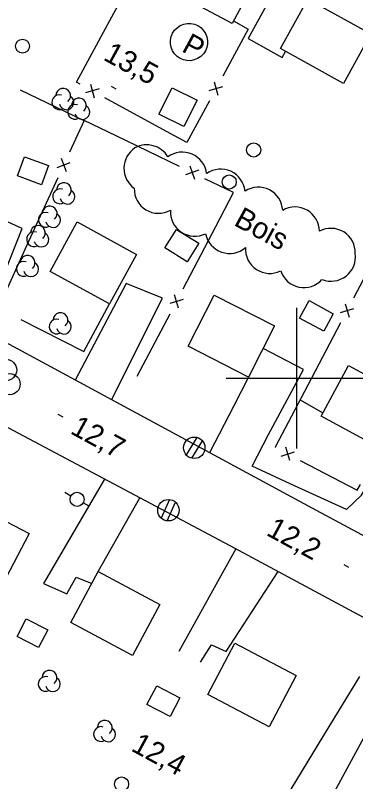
# Model space of a CAD drawing. Extents: x 219136 to 222520, y 5421589 to 5424530.
# Drawn here: x 220760 to 220808.4, y 5423742.7 to 5423851.5 of the extents above; entities that cross this region are included whole.
import ezdxf

# ---------------------------------------------------------------- set-up
doc = ezdxf.new("R2010")
doc.units = 0
for name, color, linetype in [('Level 19', 7, 'Continuous'), ('Level 21', 7, 'Continuous'), ('Level 3', 7, 'Continuous'), ('Level 31', 7, 'Continuous'), ('Level 36', 7, 'Continuous'), ('Level 37', 7, 'Continuous'), ('Level 38', 7, 'Continuous'), ('Level 44', 7, 'Continuous'), ('Level 61', 7, 'Continuous')]:
    doc.layers.add(name, color=color, linetype=linetype)

msp = doc.modelspace()

# ---------------------------------------------------------------- linework, layer by layer
at = {"layer": 'Level 19'}
for points in [[(220802.57, 5423865.48), (220793.1, 5423848.23), (220797.96, 5423845.52), (220798.42, 5423846.39)], [(220755.21, 5423806.76), (220761, 5423821.25), (220755.05, 5423823.88)], [(220773.67, 5423796.92), (220780.95, 5423811.36), (220775.79, 5423813.44), (220768.51, 5423799.7)], [(220793.68, 5423787.51), (220795.99, 5423792.01), (220800.96, 5423801.23), (220795.24, 5423804.2)], [(220793.17, 5423800.13), (220791.08, 5423796.04), (220787.59, 5423789.41)], [(220807.06, 5423781.33), (220809.21, 5423783.37), (220813.55, 5423790.78), (220817.55, 5423797.92), (220823.91, 5423794.35)], [(220772.67, 5423785.65), (220764.02, 5423770.85), (220767.36, 5423769.35), (220768.68, 5423771.74), (220770.89, 5423770.83)], [(220771.79, 5423772.53), (220777.71, 5423782.98)], [(220791.36, 5423775.74), (220783.25, 5423761.17)], [(220786.35, 5423759.65), (220787.88, 5423762.11), (220789.96, 5423761.17), (220797.37, 5423772.51)], [(220811.71, 5423752.96), (220805.01, 5423740.58), (220808.49, 5423738.12), (220812.45, 5423743.9), (220814.7, 5423746.55), (220816.11, 5423745.96)]]:
    msp.add_lwpolyline(points, dxfattribs=at)
at = {"layer": 'Level 21'}
for points in [[(220948.95, 5423703), (220904.47, 5423726.78), (220853.86, 5423753.84), (220802.2, 5423781.53), (220756.87, 5423805.98), (220752.54, 5423808.02), (220749.08, 5423809.42), (220742.93, 5423811.71), (220736.7, 5423813.64), (220729.21, 5423815.61), (220722.71, 5423817.16), (220715.9, 5423818.25), (220709.13, 5423819.02), (220700.46, 5423819.59), (220693.39, 5423819.74), (220687.57, 5423819.54), (220678.98, 5423818.61), (220672.46, 5423817.66), (220660.87, 5423814.84)], [(220837.82, 5423743.23), (220837.67, 5423747.47), (220836.68, 5423750.08), (220835.42, 5423751.94), (220834.1, 5423752.79), (220790.53, 5423776.18), (220757.42, 5423793.74), (220751.89, 5423796.6), (220745.6, 5423799.45), (220739.31, 5423801.83), (220731.18, 5423804.33), (220723.66, 5423806.27), (220711.25, 5423808.22), (220700.8, 5423809.13), (220692.45, 5423809.16), (220680.51, 5423808.54), (220669.68, 5423806.84), (220660.39, 5423804.75)], [(220807.06, 5423781.33), (220799.71, 5423784.69), (220793.68, 5423787.51)]]:
    msp.add_lwpolyline(points, dxfattribs=at)
at = {"layer": 'Level 3'}
for p, q in [((220773.62, 5423841.46), (220774.31, 5423841.08)), ((220766.06, 5423794.86), (220766.76, 5423794.48)), ((220806.69, 5423773.54), (220807.39, 5423773.16))]:
    msp.add_line(p, q, dxfattribs=at)
at = {"layer": 'Level 31'}
for points in [[(220790.84, 5423850.38), (220781.93, 5423855.16), (220785.84, 5423862.45), (220788.61, 5423860.97), (220789.07, 5423861.82), (220791.43, 5423860.55), (220790.94, 5423859.65), (220794.72, 5423857.62)], [(220806.65, 5423841.82), (220797.68, 5423846.8), (220801.59, 5423853.85), (220810.56, 5423848.88)], [(220783.96, 5423835.71), (220780.43, 5423837.48), (220782.31, 5423841.22), (220785.84, 5423839.45)], [(220761.31, 5423831.44), (220764.73, 5423830.18), (220763.73, 5423827.47), (220760.31, 5423828.73)], [(220773.38, 5423810.53), (220764.95, 5423815.15), (220768.8, 5423822.18), (220777.23, 5423817.55)], [(220782.9, 5423821.12), (220786.08, 5423819.16), (220784.46, 5423816.53), (220781.28, 5423818.49)], [(220793.17, 5423800.13), (220784.56, 5423804.52), (220788.27, 5423811.79), (220796.87, 5423807.4)], [(220801.77, 5423811), (220805.19, 5423809.14), (220803.85, 5423806.65), (220800.42, 5423808.51)], [(220811.96, 5423789.98), (220803.48, 5423794.58), (220807.38, 5423801.77), (220815.86, 5423797.18)], [(220753.23, 5423782.48), (220761.98, 5423777.92), (220758.1, 5423770.48), (220749.35, 5423775.04)], [(220771.79, 5423772.53), (220780.54, 5423767.87), (220776.68, 5423760.62), (220767.93, 5423765.27)], [(220763.33, 5423761.72), (220760.27, 5423763.32), (220761.58, 5423765.82), (220764.64, 5423764.23)], [(220791.22, 5423762.37), (220799.92, 5423757.78), (220796.07, 5423750.48), (220787.37, 5423755.07)], [(220782, 5423751.93), (220778.73, 5423753.64), (220780.13, 5423756.31), (220783.4, 5423754.6)]]:
    msp.add_lwpolyline(points, close=True, dxfattribs=at)
at = {"layer": 'Level 36'}
for p, q in [((220785.81, 5423791.57), (220784.3, 5423789.1)), ((220785.09, 5423788.63), (220786.6, 5423791.1)), ((220767.05, 5423783.78), (220767.92, 5423783.28)), ((220770.53, 5423781.8), (220769.65, 5423782.28)), ((220781.92, 5423782.74), (220780.75, 5423780.09)), ((220781.6, 5423779.74), (220782.77, 5423782.39))]:
    msp.add_line(p, q, dxfattribs=at)
for centre, radius in [((220761.04, 5423847.14), 1), ((220793.89, 5423832.4), 1), ((220790.42, 5423827.85), 1), ((220758.72, 5423801.15), 1.5), ((220759.21, 5423799.14), 1.5), ((220785.44, 5423790.1), 1.52), ((220768.79, 5423782.78), 1), ((220781.77, 5423781.24), 1.52), ((220775.12, 5423742.35), 1)]:
    msp.add_circle(centre, radius, dxfattribs=at)
at = {"layer": 'Level 37'}
for p, q in [((220788.26, 5423842.08), (220788.82, 5423840.16)), ((220771.92, 5423841.06), (220770, 5423840.49)), ((220770.68, 5423841.73), (220771.24, 5423839.81)), ((220787.58, 5423840.84), (220789.5, 5423841.41)), ((220766.55, 5423831.22), (220767.24, 5423829.34)), ((220765.95, 5423829.93), (220767.83, 5423830.63)), ((220784.82, 5423830.13), (220785.48, 5423828.24)), ((220786.09, 5423829.52), (220784.2, 5423828.86)), ((220783.23, 5423809.93), (220782.63, 5423811.84)), ((220783.88, 5423811.18), (220781.97, 5423810.59)), ((220806.88, 5423810.55), (220807.47, 5423808.64)), ((220806.21, 5423809.3), (220808.13, 5423809.89)), ((220799.05, 5423788.28), (220798.45, 5423790.19)), ((220797.79, 5423788.93), (220799.7, 5423789.53))]:
    msp.add_line(p, q, dxfattribs=at)
for points in [[(220773.18, 5423850.28), (220777.38, 5423858.03), (220778.44, 5423857.49)], [(220791.02, 5423850.72), (220793.12, 5423849.56), (220789.49, 5423842.88)], [(220769.21, 5423841.73), (220768.69, 5423842.01), (220773.18, 5423850.28)], [(220769.78, 5423836.55), (220760.77, 5423840.89)], [(220781.5, 5423835.03), (220772.72, 5423839.82)], [(220787.59, 5423839.36), (220784.38, 5423833.46), (220781.5, 5423835.03)], [(220774.34, 5423834.41), (220769.8, 5423836.6), (220767.73, 5423832.1)], [(220783.35, 5423830.06), (220774.34, 5423834.41)], [(220766.06, 5423828.46), (220761.88, 5423819.38)], [(220788.5, 5423821.51), (220791.04, 5423826.34), (220786.95, 5423828.32)], [(220783.86, 5423812.66), (220788.5, 5423821.51)], [(220761.88, 5423819.38), (220757.7, 5423810.29)], [(220814.52, 5423814.66), (220810.84, 5423816.55), (220808.1, 5423811.36)], [(220769.74, 5423803.8), (220769.77, 5423803.79), (220773.38, 5423810.53)], [(220760.82, 5423808.33), (220769.74, 5423803.8)], [(220777.35, 5423800.26), (220782, 5423809.11)], [(220806.24, 5423807.83), (220801.57, 5423798.98)], [(220801.57, 5423798.98), (220796.93, 5423790.18), (220796.97, 5423790.16)], [(220800.48, 5423796.9), (220803.74, 5423795.05)], [(220800.52, 5423788.31), (220808.59, 5423784.1), (220809.05, 5423784.88)], [(220803.76, 5423749.09), (220808.97, 5423757.63)], [(220798.56, 5423740.55), (220803.76, 5423749.09)]]:
    msp.add_lwpolyline(points, dxfattribs=at)
at = {"layer": 'Level 38'}
msp.add_ellipse((220784.69, 5423847.72), major_axis=(-1.24, 2.34), ratio=0.999955, dxfattribs=at)
at = {"layer": 'Level 44'}
for centre, radius, start, end in [((220766.81, 5423840.09), 1.05, 310.1588, 177.6158), ((220766.26, 5423839.2), 1.05, 72.005, 297.6935), ((220767.3, 5423839.16), 1.05, 194.8265, 57.5108), ((220768.51, 5423837.83), 1.05, 72.005, 297.6935), ((220769.06, 5423838.72), 1.05, 310.1588, 177.6158), ((220769.55, 5423837.79), 1.05, 194.8265, 57.5108), ((220778.91, 5423829.79), 3.46, 123.313, 234.8249), ((220778.71, 5423829.67), 3.46, 30.1731, 119.2766), ((220783.77, 5423828.63), 3.46, 6.7804, 126.7804), ((220789.22, 5423826.22), 3.46, 5.4865, 125.4865), ((220766.38, 5423825.81), 1.05, 72.005, 297.6935), ((220766.93, 5423826.7), 1.05, 310.1588, 177.6158), ((220780.38, 5423826.86), 3.46, 178.3266, 299.1287), ((220794.56, 5423823.65), 3.46, 2.9717, 122.9717), ((220767.42, 5423825.77), 1.05, 194.8265, 57.5108), ((220764.35, 5423822.49), 1.05, 72.005, 297.6935), ((220764.9, 5423823.38), 1.05, 310.1588, 177.6158), ((220785.52, 5423823.61), 3.46, 176.2651, 296.2651), ((220799.77, 5423820.84), 3.46, 0.376, 120.376), ((220765.39, 5423822.45), 1.05, 194.8265, 57.5108), ((220763.23, 5423820.62), 1.05, 310.1588, 177.6158), ((220762.68, 5423819.73), 1.05, 72.005, 297.6935), ((220763.72, 5423819.69), 1.05, 194.8265, 57.5108), ((220790.46, 5423821.16), 3.46, 190.9275, 310.9275), ((220804.87, 5423817.81), 3.46, 358.1766, 118.1766), ((220796.18, 5423818.33), 3.46, 176.4737, 296.4737), ((220761.77, 5423816.39), 1.05, 310.1588, 177.6158), ((220804.9, 5423817.22), 3.46, 247.9881, 7.9881), ((220761.22, 5423815.5), 1.05, 72.005, 297.6935), ((220762.26, 5423815.46), 1.05, 194.8265, 57.5108), ((220801.02, 5423816.31), 3.46, 198.2237, 318.2237), ((220765.88, 5423807.34), 1.05, 72.005, 297.6935), ((220766.43, 5423808.23), 1.05, 310.1588, 177.6158), ((220766.92, 5423807.3), 1.05, 194.8265, 57.5108), ((220764.87, 5423757.45), 1.05, 310.1588, 177.6158), ((220764.32, 5423756.56), 1.05, 72.005, 297.6935), ((220765.36, 5423756.52), 1.05, 194.8265, 57.5108), ((220772.73, 5423750.34), 1.05, 310.1588, 177.6158), ((220772.18, 5423749.45), 1.05, 72.005, 297.6935), ((220773.22, 5423749.41), 1.05, 194.8265, 57.5108)]:
    msp.add_arc(centre, radius, start, end, dxfattribs=at)
at = {"layer": 'Level 61'}
for points in [[(220800, 5423810), (220800, 5423800), (220800, 5423790)], [(220790, 5423800), (220800, 5423800), (220810, 5423800)]]:
    msp.add_lwpolyline(points, dxfattribs=at)

# ---------------------------------------------------------------- texts
at = {"layer": 'Level 3'}
for s, p in [('13,5', (220772.37, 5423845.27)), ('12,7', (220767.68, 5423792.22)), ('12,2', (220795.53, 5423777.78)), ('12,4', (220776.32, 5423747.16))]:
    msp.add_text(s, height=3, rotation=331.383, dxfattribs=at).set_placement(p)
at = {"layer": 'Level 38'}
msp.add_text('P', height=3, rotation=331.383, dxfattribs=at).set_placement((220783.51, 5423846.48))
at = {"layer": 'Level 44'}
msp.add_text('Bois', height=3, rotation=331.3547, dxfattribs=at).set_placement((220790.92, 5423821.79))

doc.saveas('drawing.dxf')
